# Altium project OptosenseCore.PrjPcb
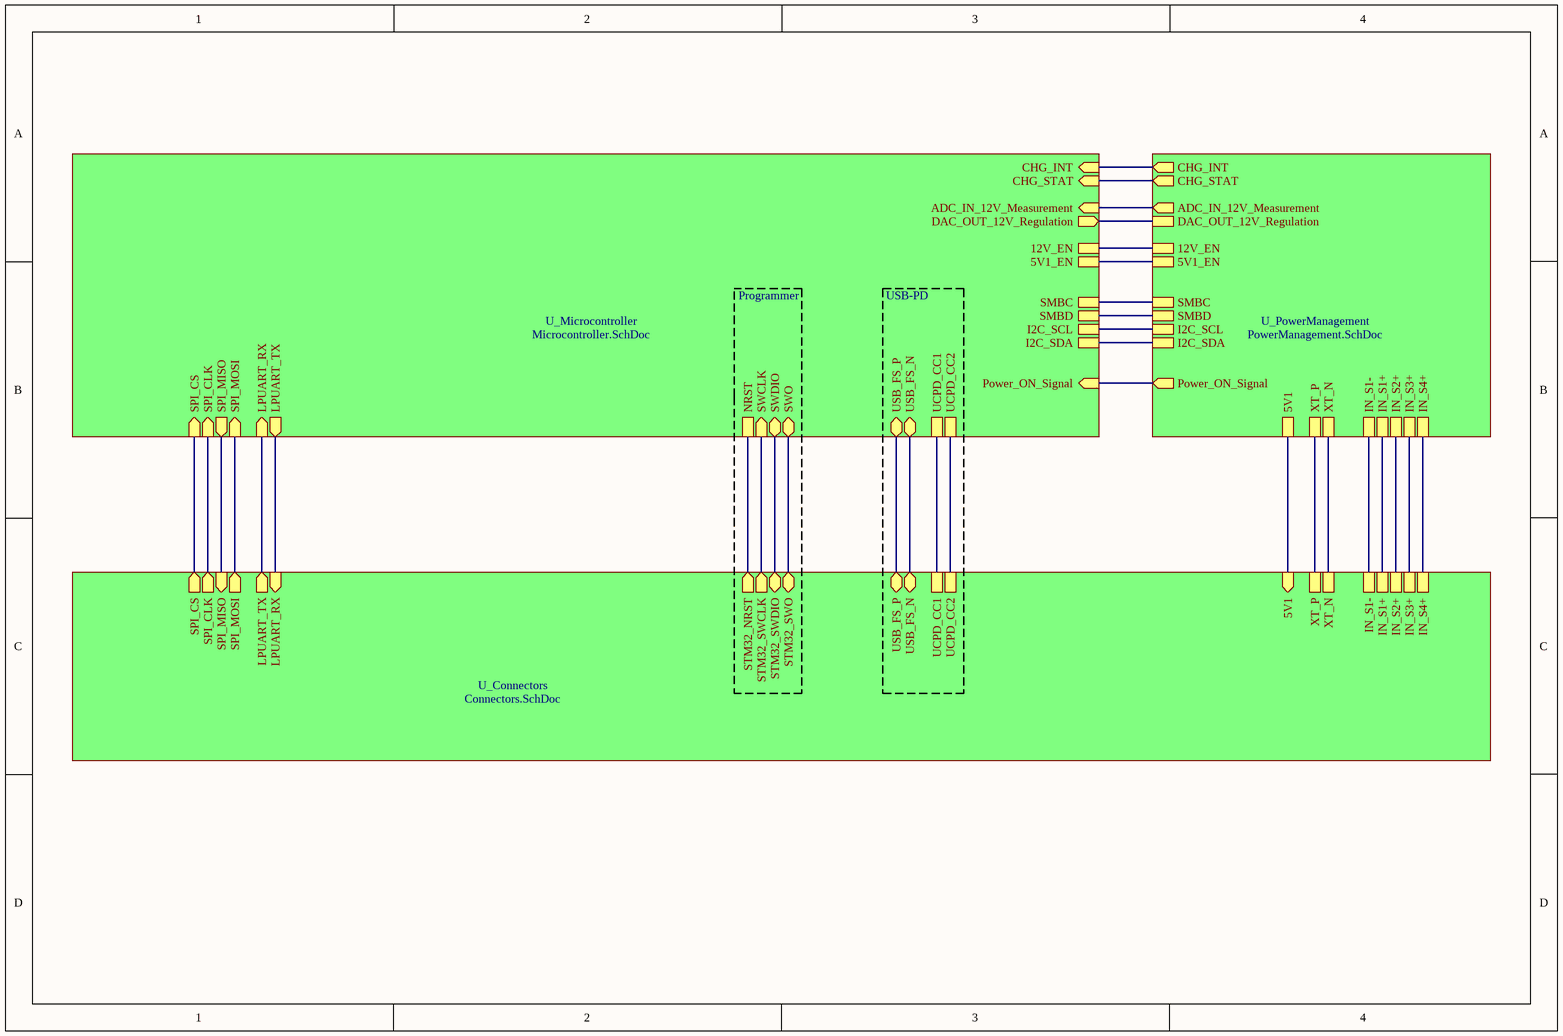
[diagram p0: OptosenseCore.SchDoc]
4 sheets, 184 parts. Net scope: hierarchical (ports join the sheet entries above them; power ports are global).
Board file: OptosenseCore.PcbDoc
Sheets:
  OptosenseCore.SchDoc
    U_Connectors = Connectors.SchDoc
    U_PowerManagement = PowerManagement.SchDoc
    U_Microcontroller = Microcontroller.SchDoc

## Sheet OptosenseCore.SchDoc
size A4

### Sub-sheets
U_Connectors = Connectors.SchDoc: 5V1 (in), SPI_CLK (out), SPI_MISO (in), SPI_MOSI (out), SPI_CS (out), STM32_SWDIO (bidir), STM32_SWO (bidir), STM32_SWCLK (out), USB_FS_P (bidir), USB_FS_N (bidir), UCPD_CC1, UCPD_CC2, LPUART_TX (out), LPUART_RX (in), STM32_NRST (out), XT_P, IN_S2+, IN_S3+, IN_S4+, IN_S1-, XT_N, IN_S1+
U_Microcontroller = Microcontroller.SchDoc: SWO (bidir), SWDIO (bidir), LPUART_RX (in), LPUART_TX (out), SPI_MISO (out), SPI_CLK (in), SPI_CS (in), SPI_MOSI (in), SWCLK (in), UCPD_CC1, UCPD_CC2, USB_FS_P (bidir), USB_FS_N (bidir), DAC_OUT_12V_Regulation (out), I2C_SCL, NRST, I2C_SDA, SMBC, SMBD, 12V_EN, 5V1_EN, CHG_INT (in), Power_ON_Signal (in), CHG_STAT (in), ADC_IN_12V_Measurement (in)
U_PowerManagement = PowerManagement.SchDoc: IN_S3+, IN_S4+, IN_S1-, IN_S1+, IN_S2+, XT_P, XT_N, I2C_SDA, SMBC, SMBD, I2C_SCL, 5V1, 12V_EN, DAC_OUT_12V_Regulation, 5V1_EN, CHG_INT (out), Power_ON_Signal (out), CHG_STAT (out), ADC_IN_12V_Measurement (out)

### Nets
CHG_INT: sheet U_PowerManagement/CHG_INT, sheet U_Microcontroller/CHG_INT
DIFF_USB_FS_N: sheet U_Connectors/USB_FS_N, sheet U_Microcontroller/USB_FS_N
DIFF_USB_FS_P: sheet U_Connectors/USB_FS_P, sheet U_Microcontroller/USB_FS_P
I2C_SCL: sheet U_PowerManagement/I2C_SCL, sheet U_Microcontroller/I2C_SCL
I2C_SDA: sheet U_PowerManagement/I2C_SDA, sheet U_Microcontroller/I2C_SDA
IO.PA0: sheet U_PowerManagement/ADC_IN_12V_Measurement, sheet U_Microcontroller/ADC_IN_12V_Measurement
IO.PA2: sheet U_Connectors/LPUART_RX, sheet U_Microcontroller/LPUART_TX
IO.PA3: sheet U_Connectors/LPUART_TX, sheet U_Microcontroller/LPUART_RX
IO.PA4: sheet U_PowerManagement/DAC_OUT_12V_Regulation, sheet U_Microcontroller/DAC_OUT_12V_Regulation
IO.PA5: sheet U_Connectors/SPI_CLK, sheet U_Microcontroller/SPI_CLK
IO.PA6: sheet U_Connectors/SPI_MISO, sheet U_Microcontroller/SPI_MISO
IO.PA7: sheet U_Connectors/SPI_MOSI, sheet U_Microcontroller/SPI_MOSI
IO.PA8: sheet U_PowerManagement/5V1_EN, sheet U_Microcontroller/5V1_EN
IO.PA10: sheet U_PowerManagement/12V_EN, sheet U_Microcontroller/12V_EN
IO.PA13: sheet U_Connectors/STM32_SWDIO, sheet U_Microcontroller/SWDIO
IO.PA14: sheet U_Connectors/STM32_SWCLK, sheet U_Microcontroller/SWCLK
IO.PA15: sheet U_Connectors/UCPD_CC1, sheet U_Microcontroller/UCPD_CC1
IO.PB0: sheet U_Connectors/SPI_CS, sheet U_Microcontroller/SPI_CS
IO.PB2: sheet U_PowerManagement/CHG_STAT, sheet U_Microcontroller/CHG_STAT
IO.PB3: sheet U_Connectors/STM32_SWO, sheet U_Microcontroller/SWO
IO.PB10: sheet U_PowerManagement/SMBC, sheet U_Microcontroller/SMBC
IO.PB11: sheet U_PowerManagement/SMBD, sheet U_Microcontroller/SMBD
IO.PB14: sheet U_Connectors/UCPD_CC2, sheet U_Microcontroller/UCPD_CC2
IO.PC13: sheet U_PowerManagement/Power_ON_Signal, sheet U_Microcontroller/Power_ON_Signal
NRST: sheet U_Connectors/STM32_NRST, sheet U_Microcontroller/NRST
XT_N: sheet U_Connectors/IN_S1-, sheet U_Connectors/XT_N, sheet U_PowerManagement/IN_S1-, sheet U_PowerManagement/XT_N
XT_P: sheet U_Connectors/XT_P, sheet U_Connectors/IN_S4+, sheet U_PowerManagement/IN_S4+, sheet U_PowerManagement/XT_P
NetR44_1: sheet U_Connectors/IN_S3+, sheet U_PowerManagement/IN_S3+
NetR45_1: sheet U_Connectors/IN_S2+, sheet U_PowerManagement/IN_S2+
NetR46_1: sheet U_Connectors/IN_S1+, sheet U_PowerManagement/IN_S1+
(unnamed): sheet U_Connectors/5V1, sheet U_PowerManagement/5V1

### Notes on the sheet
- Programmer
- USB-PD

## Sheet Connectors.SchDoc
size A3
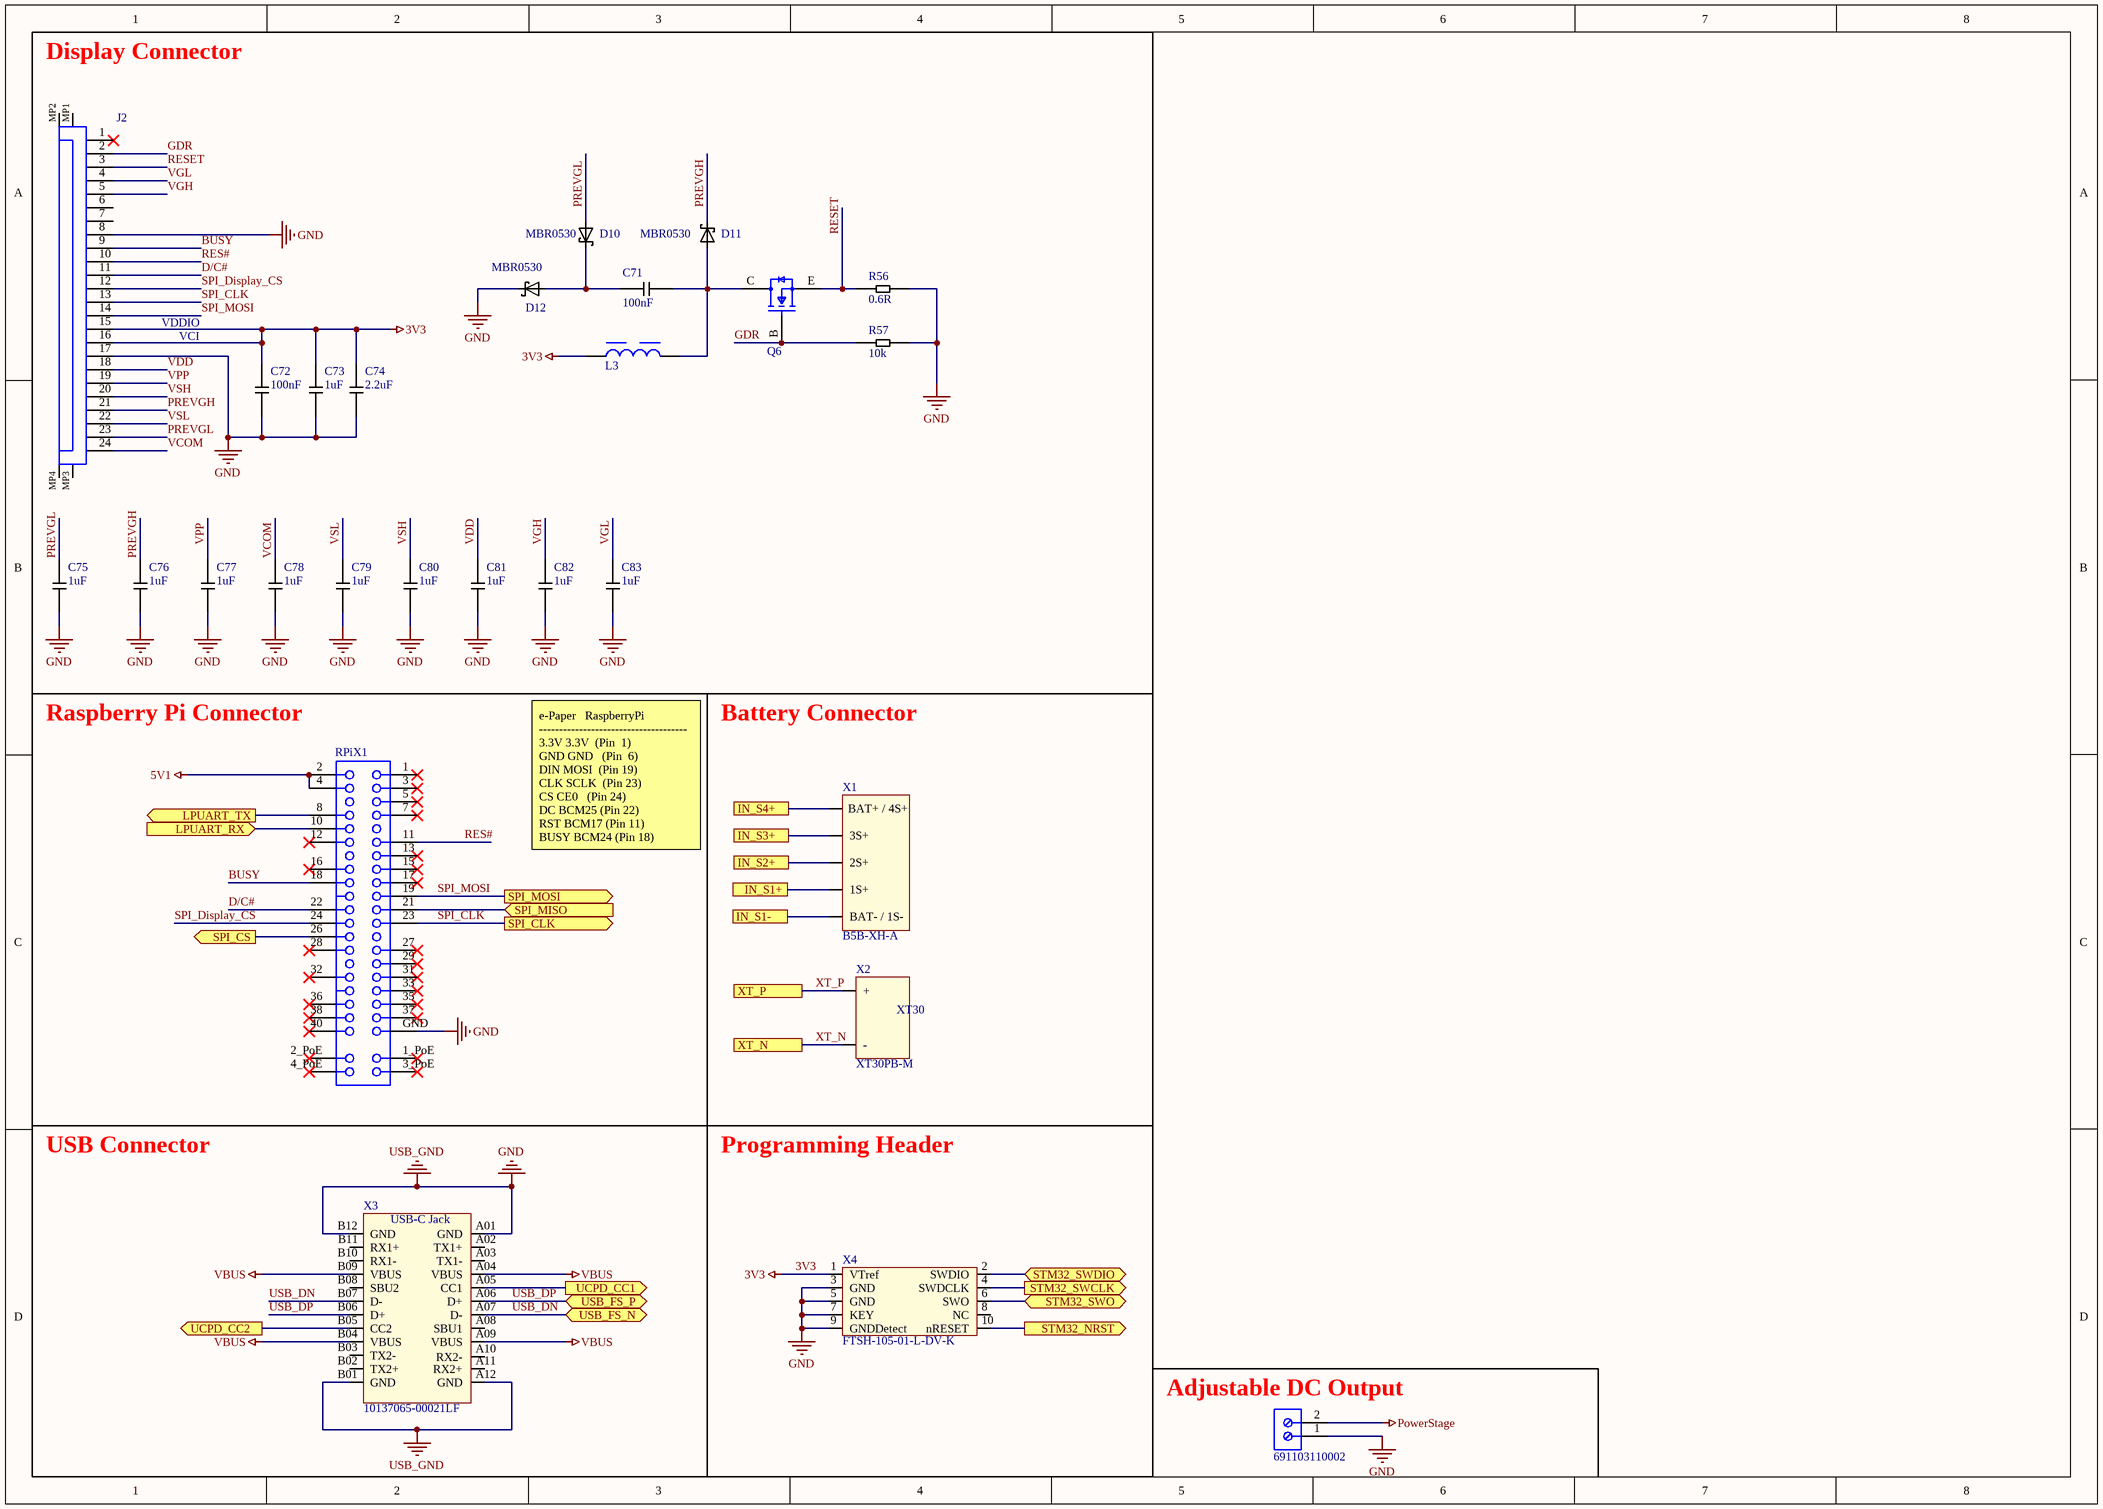
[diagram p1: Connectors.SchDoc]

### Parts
C71  100nF  [C_0402]
C72  100nF  [C_0402]
C73  1uF  [C_0402]
C74  2.2uF  [C_0402]
C75  1uF  [C_0402]
C76  1uF  [C_0402]
C77  1uF  [C_0402]
C78  1uF  [C_0402]
C79  1uF  [C_0402]
C80  1uF  [C_0402]
C81  1uF  [C_0402]
C82  1uF  [C_0402]
C83  1uF  [C_0402]
D10  MBR0530  [*SOD123_MBR0530(Primary)]
D11  MBR0530  [*SOD123_MBR0530(Primary)]
D12  MBR0530  [*SOD123_MBR0530(Primary)]
J2  (no value)  [687324124422]
J_Interlock1  691103110002  [691103110002]
L3  68µH, 0.45A  [WE-LQS_4012]  (value not drawn)
Q6  *  [SOT-23-3]  (value not drawn)
R56  0.6R  [R_0402]
R57  10k  [R_0402]
RPiX1  (no value)  [RPi - PoE Hole]
X1  B5B-XH-A  [X_XH5]
X2  XT30PB-M  [X_XT30_90°]
X3  10137065-00021LF  [X_USBC_JACK]
X4  FTSH-105-01-L-DV-K  [SAMTEC_FTSH-105-01-L-DV-K]

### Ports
IN_S1+, IN_S1-, IN_S2+, IN_S3+, IN_S4+, LPUART_RX (in), LPUART_TX (out), SPI_CLK (out), SPI_CS (out), SPI_MISO (in), SPI_MOSI (out), STM32_NRST (out), STM32_SWCLK (out), STM32_SWDIO (bidir), STM32_SWO (bidir), UCPD_CC1 (out), UCPD_CC2 (out), USB_FS_N (bidir), USB_FS_P (bidir), XT_N, XT_P

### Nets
3V3: C72.2 C73.2 C74.2 J2.15 J2.16 L3.1 X4.1(VTref)
5V1: RPiX1.2 RPiX1.4
GND: C72.1 C73.1 C74.1 C75.1 C76.1 C77.1 C78.1 C79.1 C80.1 C81.1 C82.1 C83.1 D12.C J2.8 J2.17 J_Interlock1.1 R56.1 R57.1 RPiX1.GND X3.A01(GND) X3.A12(GND) X3.B01(GND) X3.B12(GND) X4.3(GND) X4.5(GND) X4.7(KEY) X4.9(GNDDetect)  [also labelled USB_GND]
PowerStage: J_Interlock1.2
VBUS: X3.A04(VBUS) X3.A09(VBUS) X3.B04(VBUS) X3.B09(VBUS)
BUSY: J2.9 RPiX1.18
D/C#: J2.11 RPiX1.22
GDR: J2.2 Q6.B(Gate) R57.2
IO.PA2: RPiX1.10 ; port LPUART_RX
IO.PA3: RPiX1.8 ; port LPUART_TX
IO.PA6: RPiX1.21 ; port SPI_MISO
IO.PA13: X4.2(SWDIO) ; port STM32_SWDIO
IO.PA14: X4.4(SWDCLK) ; port STM32_SWCLK
IO.PA15: X3.A05(CC1) ; port UCPD_CC1
IO.PB0: RPiX1.26 ; port SPI_CS
IO.PB3: X4.6(SWO) ; port STM32_SWO
IO.PB14: X3.B05(CC2) ; port UCPD_CC2
NRST: X4.10(nRESET) ; port STM32_NRST
PREVGH: C76.2 D11.C J2.21
PREVGL: C75.2 D10.A J2.23
RES#: J2.10 RPiX1.11
RESET: J2.3 Q6.E(Source) R56.2
SPI_CLK: J2.13 RPiX1.23 ; port SPI_CLK  [project net IO.PA5]
SPI_Display_CS: J2.12 RPiX1.24
SPI_MOSI: J2.14 RPiX1.19 ; port SPI_MOSI  [project net IO.PA7]
USB_DN: X3.A07(D-) X3.B07(D-) ; port USB_FS_N  [project net DIFF_USB_FS_N]
USB_DP: X3.A06(D+) X3.B06(D+) ; port USB_FS_P  [project net DIFF_USB_FS_P]
VCOM: C78.2 J2.24
VDD: C81.2 J2.18
VGH: C82.2 J2.5
VGL: C83.2 J2.4
VPP: C77.2 J2.19
VSH: C80.2 J2.20
VSL: C79.2 J2.22
XT_N: X1.1(BAT-_/_1S-) X2.2(-) ; port XT_N, port IN_S1-
XT_P: X1.5(BAT+_/_4S+) X2.1(+) ; port XT_P, port IN_S4+
NetC71_1: C71.1 D11.A L3.2 Q6.C
NetC71_2: C71.2 D10.C D12.A
NetR44_1: X1.4(3S+) ; port IN_S3+
NetR45_1: X1.3(2S+) ; port IN_S2+
NetR46_1: X1.2(1S+) ; port IN_S1+

Not connected (* = marked no-connect by the designer): J2 1* 6 7 MP1 MP2 MP3 MP4; RPiX1 1* 1_PoE* 2_PoE* 3* 3_PoE* 4_PoE* 5* 7* 12* 13* 15* 16* 17* 27* 28* 29* 31* 32* 33* 35* 36* 37* 38* 40*; X3 A02(TX1+) A03(TX1-) A08(SBU1) A10(RX2-) A11(RX2+) B02(TX2+) B03(TX2-) B08(SBU2) B10(RX1-) B11(RX1+); X4 8(NC)

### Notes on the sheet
- Display Connector
- VDDIO
- VCI
- (near RPiX1) Raspberry Pi Connector
- Battery Connector
- e-Paper  	RaspberryPi
  -------------------------------------
  3.3V	3.3V 	(Pin  1)
  GND	GND  	(Pin  6)
  DIN	MOSI 	(Pin 19)
  CLK	SCLK 	(Pin 23)
  CS	CE0  	(Pin 24)
  DC	BCM25	(Pin 22)
  RST	BCM17	(Pin 11)
  BUSY	BCM24	(Pin 18)
- USB Connector
- Programming Header
- (near J_Interlock1) Adjustable DC Output

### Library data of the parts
C71 C72 C74 = C_X_0402
C73 C75-C83 = C_X_0402: 50V
D10-D12 = MBR0530: BAT54W-HG3-08
J2 = 687324124422: WR-FPC SMT ZIF Vertical, pitch 0.5mm, 24p; Contact Resistance: 20mOhm; Pin Number: 24; Working Voltage: 50VAC; Rated Current: 0.5A
J_Interlock1 = 691103110002: WR-TBL Serie 1031 Horizontal Entry Modular, Pressure Clamp, THT, pitch 3.5mm, 2p; Manufacturer: Wurth Elektronik; Modularity: Yes; PCB/Cable/Panel: PCB; Pin Number: 2; Rated Current [UL]: 10A; Working Voltage [UL]: 125VAC
L3 = 74404041680: WE-LQS SMT Power Inductor, size 4012, 68µH, 0.45A, 1.495Ω; Manufacturer: Wurth Elektronik; Case/Size Code: 4012; Saturation Current: 0.48A; Self Resonant Frequency: 13MHz
Q6 = NTR4170NT1G
R56 R57 = R_X_0402
RPiX1 = RPi: WR-PHD Socket Header, SMT, pitch 2.54mm, Dual Row, Vertical, 40pin; Part Number: 61004021821; Pin Number: 40; Gender: Female; Rated Current: 3A; Working Voltage: 250VAC; Withstanding Voltage: 600VAC; Contact Resistance: 20mOhm
X1 = X_XH5
X2 = X_XT30PB-F-90°: XT30PB-F-90°
X3 = X_USB_TypC
X4 = X_Cortex_Debug_10

## Sheet PowerManagement.SchDoc
size A2
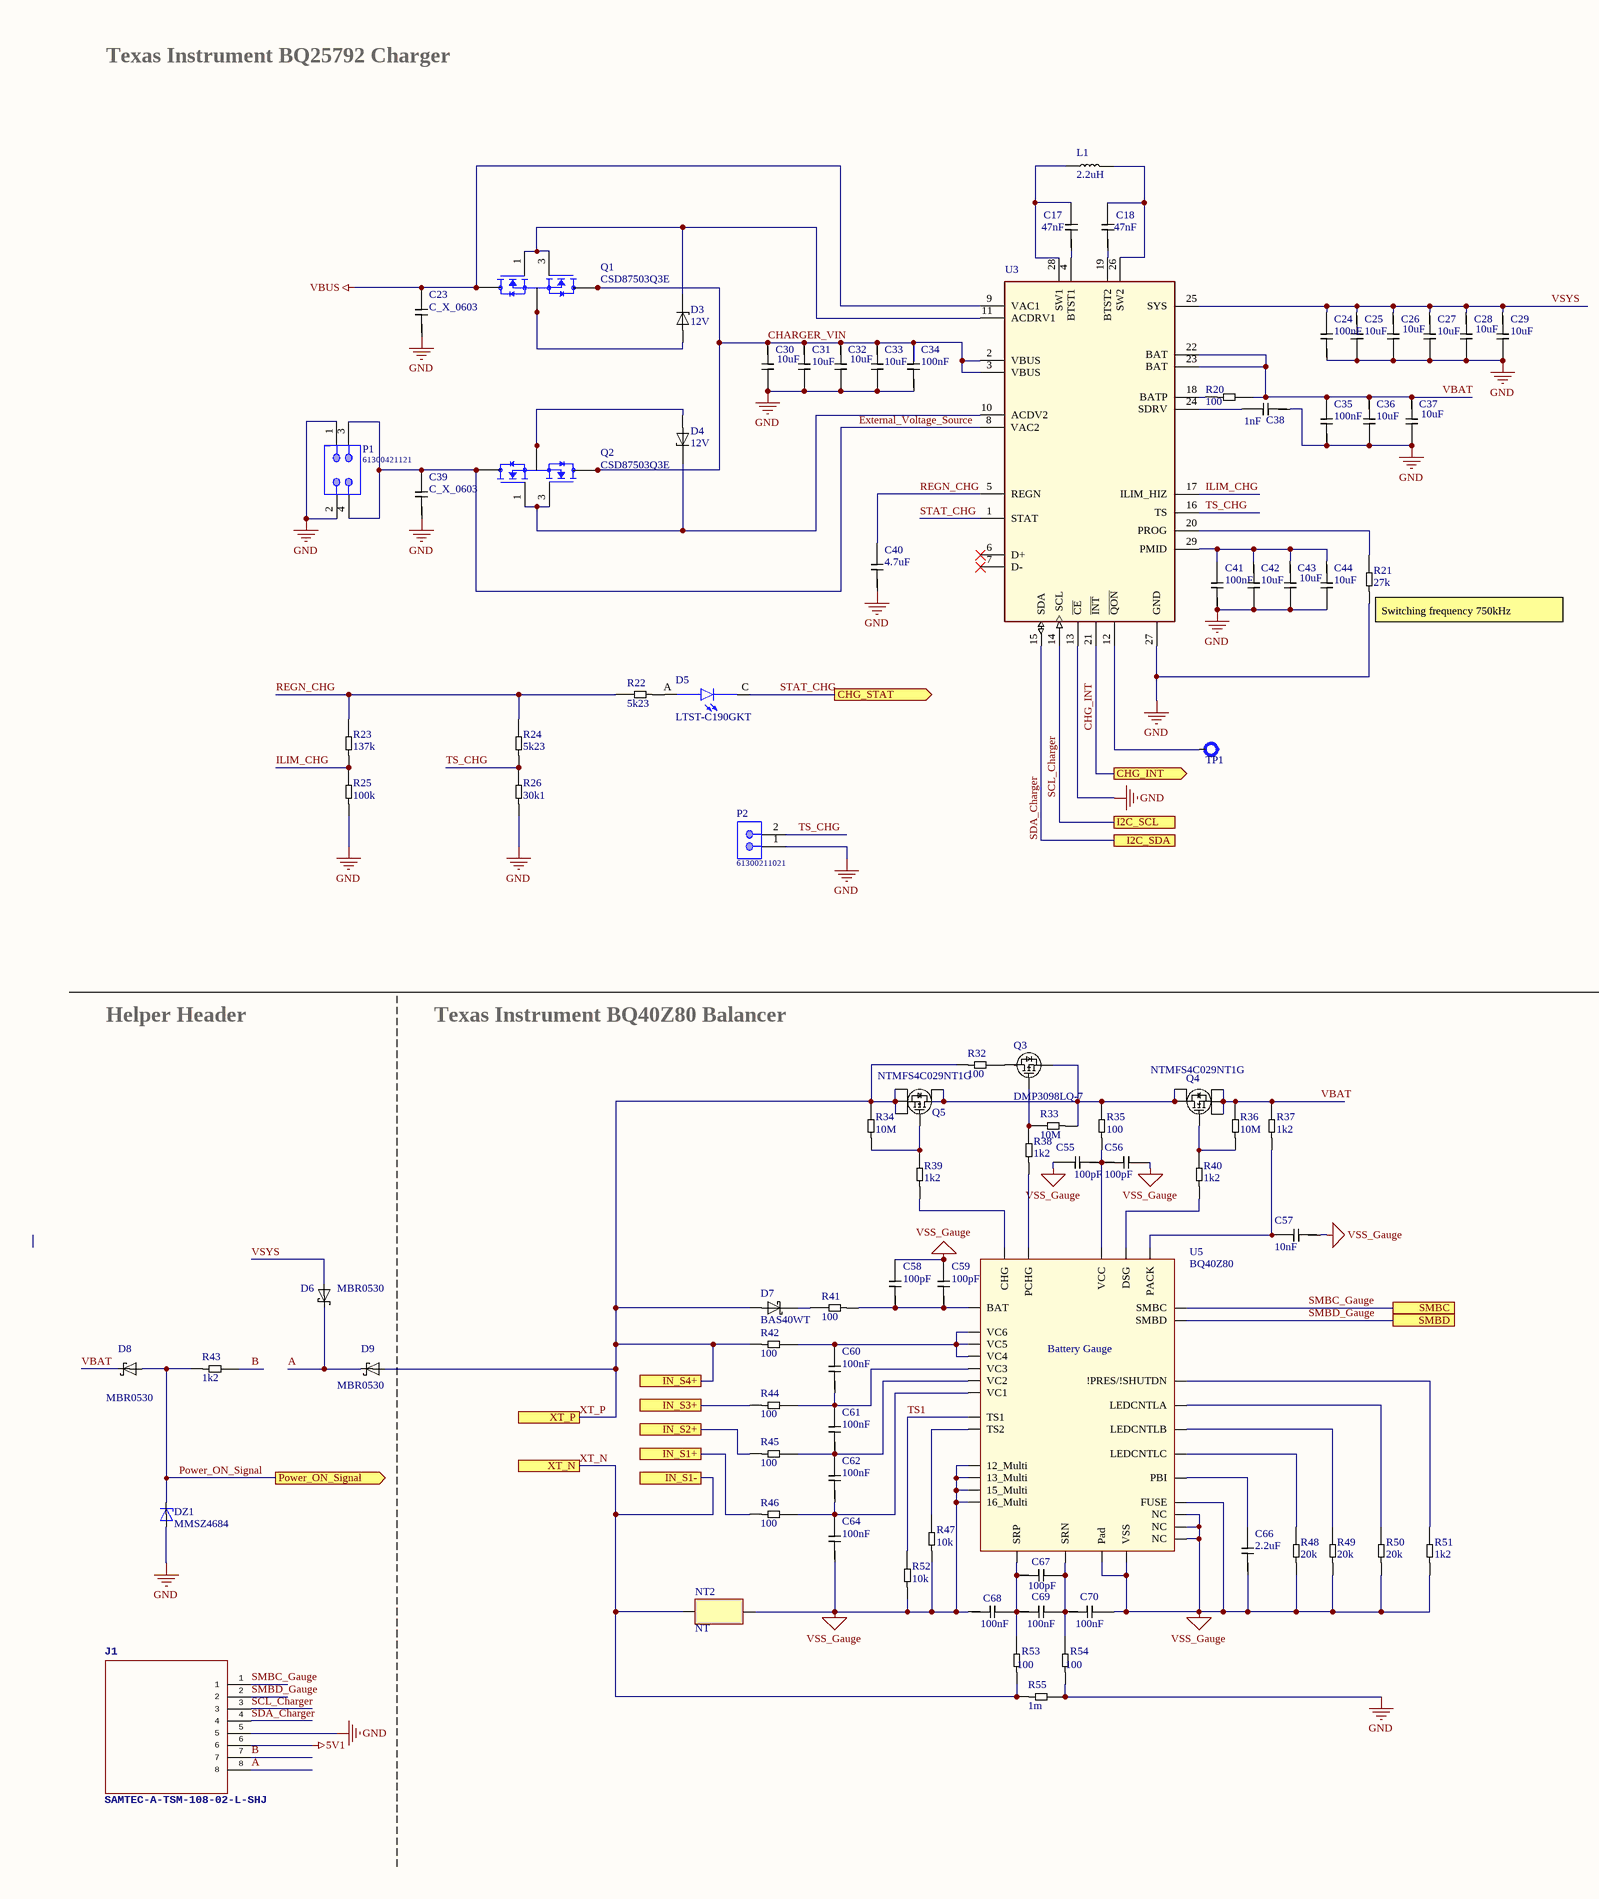
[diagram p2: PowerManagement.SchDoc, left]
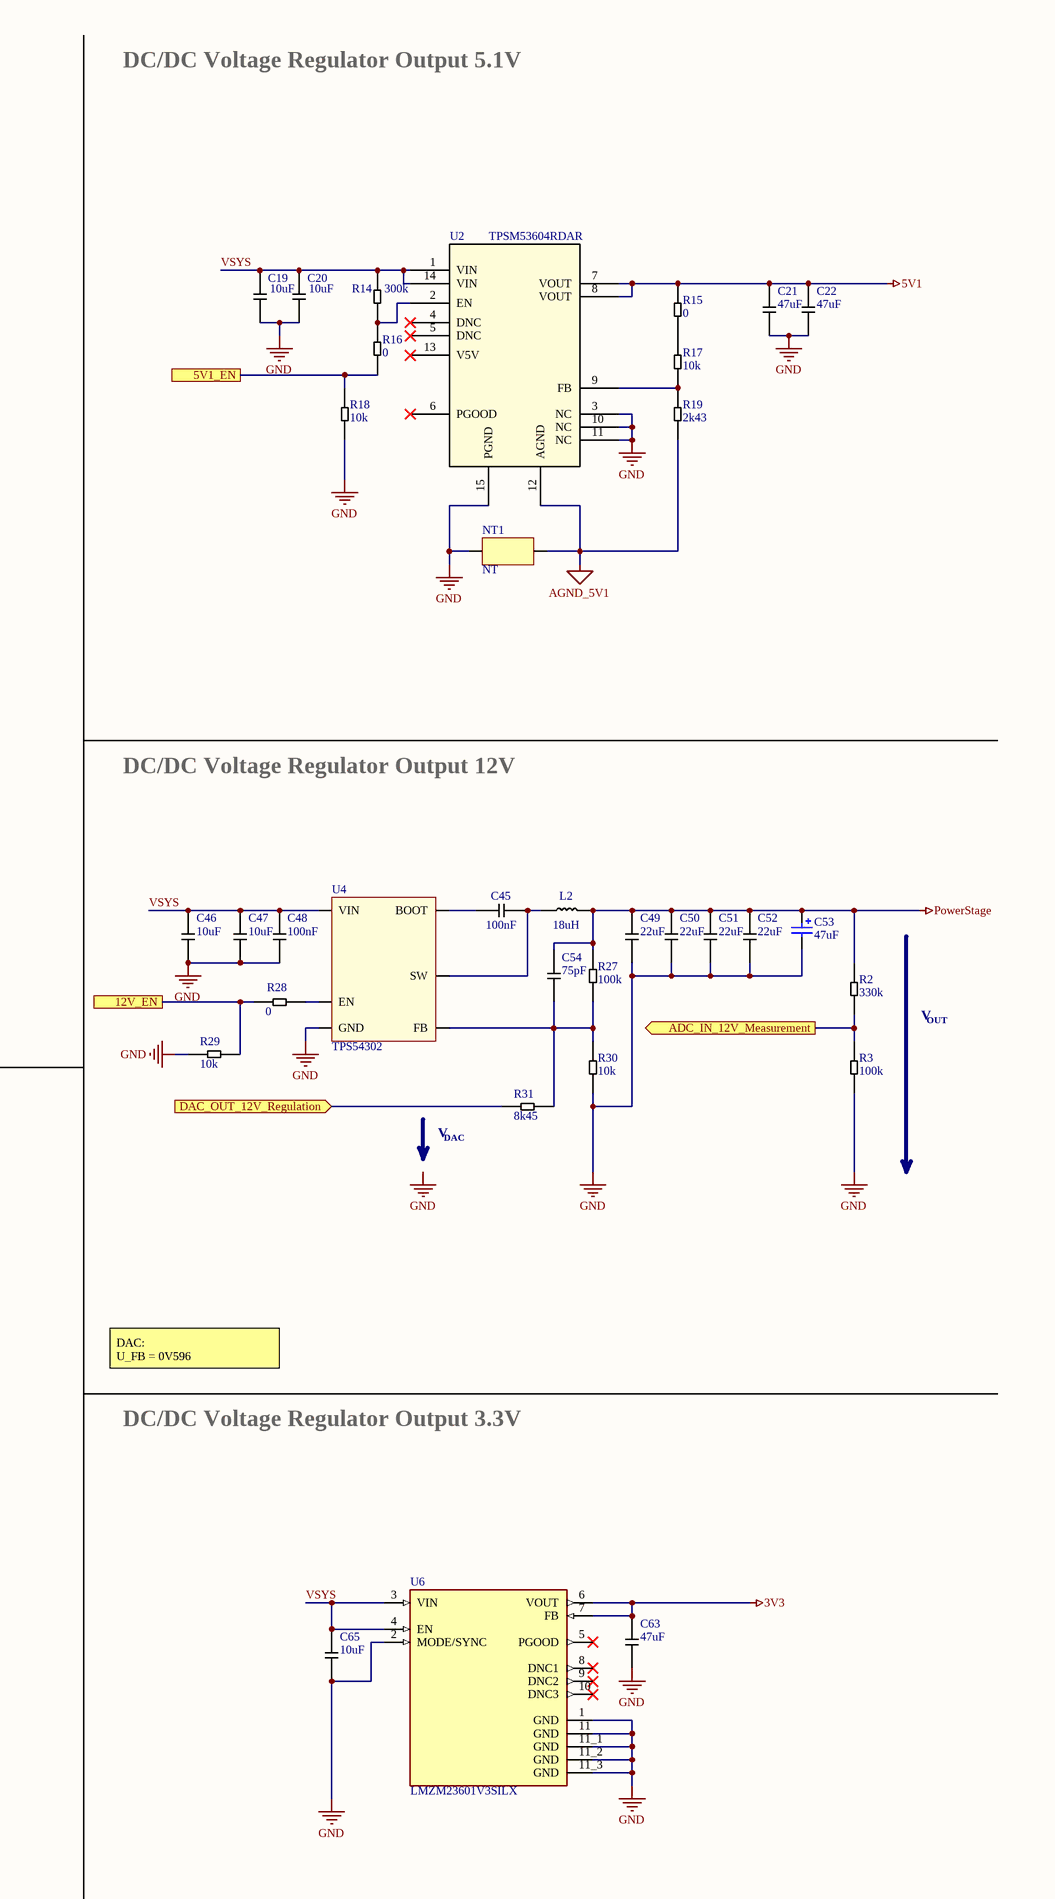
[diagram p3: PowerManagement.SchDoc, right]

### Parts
C17  47nF  [C_0603]
C18  47nF  [C_0603]
C19  10uF  [C_0805]
C20  10uF  [C_0805]
C21  47uF  [C_0805]
C22  47uF  [C_0805]
C23  C_X_0603  [C_0603]
C24  100nF  [C_0402]
C25  10uF  [C_0805]
C26  10uF  [C_0805]
C27  10uF  [C_0805]
C28  10uF  [C_0805]
C29  10uF  [C_0805]
C30  10uF  [C_0805]
C31  10uF  [C_0805]
C32  10uF  [C_0805]
C33  10uF  [C_0805]
C34  100nF  [C_0402]
C35  100nF  [C_0402]
C36  10uF  [C_0805]
C37  10uF  [C_0805]
C38  1nF  [C_0402]
C39  C_X_0603  [C_0603]
C40  4.7uF  [C_0805]
C41  100nF  [C_0402]
C42  10uF  [C_0805]
C43  10uF  [C_0805]
C44  10uF  [C_0805]
C45  100nF  [C_0402]
C46  10uF  [C_0805]
C47  10uF  [C_0805]
C48  100nF  [C_0402]
C49  22uF  [C_1206]
C50  22uF  [C_1206]
C51  22uF  [C_1206]
C52  22uF  [C_1206]
C53  47uF  [WCAP-ASLI_D6.3H5.5]
C54  75pF  [C_0402]
C55  100pF  [C_0402]
C56  100pF  [C_0402]
C57  10nF  [C_0402]
C58  100pF  [C_0402]
C59  100pF  [C_0402]
C60  100nF  [C_0402]
C61  100nF  [C_0402]
C62  100nF  [C_0402]
C63  47uF  [C_0805]
C64  100nF  [C_0402]
C65  10uF  [C_0805]
C66  2.2uF  [C_1210]
C67  100pF  [C_0402]
C68  100nF  [C_0402]
C69  100nF  [C_0402]
C70  100nF  [C_0402]
D3  12V  [MELF_SOD-80]
D4  12V  [MELF_SOD-80]
D5  LTST-C190GKT  [LEDM1608X80]
D6  MBR0530  [*SOD123_MBR0530(Primary)]
D7  BAS40WT  [SOT-323]
D8  MBR0530  [*SOD123_MBR0530(Primary)]
D9  MBR0530  [*SOD123_MBR0530(Primary)]
DZ1  MMSZ4684  [SOD-123]
J1  SAMTEC-A-TSM-108-02-L-SHJ  [SAMTEC-A-TSM-108-02-L-SH]
L1  2.2uH  [MPXV1D0630L2R2]
L2  18uH  [SRN1060]
NT1  NT  [Net Tie]  (net tie, no BOM)
NT2  NT  [Net Tie]  (net tie, no BOM)
P1  61300421121  [61300421121]
P2  61300211021  [61300211021]
Q1  CSD87503Q3E  [CSD87503Q3E]
Q2  CSD87503Q3E  [CSD87503Q3E]
Q3  DMP3098LQ-7  [SOT-23-3]
Q4  NTMFS4C029NT1G  [SO-8FL]
Q5  NTMFS4C029NT1G  [SO-8FL]
R2  330k  [R_0402]
R3  100k  [R_0402]
R14  300k  [R_0402]
R15  0  [R_0402]
R16  0  [R_0402]
R17  10k  [R_0402]
R18  10k  [R_0402]
R19  2k43  [R_0402]
R20  100  [R_0402]
R21  27k  [R_0402]
R22  5k23  [R_0402]
R23  137k  [R_0402]
R24  5k23  [R_0402]
R25  100k  [R_0402]
R26  30k1  [R_0402]
R27  100k  [R_0402]
R28  0  [R_0402]
R29  10k  [R_0402]
R30  10k  [R_0402]
R31  8k45  [R_0402]
R32  100  [R_0508_reversed]
R33  10M  [R_0402]
R34  10M  [R_0402]
R35  100  [R_0402]
R36  10M  [R_0402]
R37  1k2  [R_0402]
R38  1k2  [R_0402]
R39  1k2  [R_0402]
R40  1k2  [R_0402]
R41  100  [R_0402]
R42  100  [R_0402]
R43  1k2  [R_0402]
R44  100  [R_0402]
R45  100  [R_0402]
R46  100  [R_0402]
R47  10k  [R_0402]
R48  20k  [R_0402]
R49  20k  [R_0402]
R50  20k  [R_0402]
R51  1k2  [R_0402]
R52  10k  [R_0402]
R53  100  [R_0402]
R54  100  [R_0402]
R55  1m  [R_1206]
TP1  TP  [Testpoint]  (value not drawn)
U2  TPSM53604RDAR  [Texas_Instruments_RDA0015A_MFG]
U3  BQ25792RQMR  [Texas_Instruments_RQM0029A_MFG]  (value not drawn)
U4  TPS54302  [SOT-23-THIN]
U5  BQ40Z80  [VQFN32]
U6  LMZM23601V3SILX  [CONV_LMZM23601V3XXXX]

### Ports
5V1_EN, 12V_EN, ADC_IN_12V_Measurement (out), CHG_INT (out), CHG_STAT (out), DAC_OUT_12V_Regulation (in), I2C_SCL, I2C_SDA, IN_S1+, IN_S1-, IN_S2+, IN_S3+, IN_S4+, Power_ON_Signal (out), SMBC, SMBD, XT_N, XT_P

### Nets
3V3: C63.2 U6.6(VOUT) U6.7(FB)
5V1: C21.2 C22.2 J1.6 R15.2 U2.7(VOUT) U2.8(VOUT)
AGND_5V1: NT1.2 R19.1 U2.12(AGND)
GND: C19.2 C20.2 C21.1 C22.1 C23.1 C24.1 C25.2 C26.2 C27.2 C28.2 C29.2 C30.2 C31.2 C32.2 C33.2 C34.1 C35.1 C36.2 C37.2 C38.1 C39.1 C40.1 C41.1 C42.2 C43.2 C44.2 C46.2 C47.2 C48.1 C49.2 C50.2 C51.2 C52.2 C53.2(N) C63.1 C65.1 DZ1.A J1.5 NT1.1 P1.1 P1.2 P2.1 R3.2 R18.2 R21.1 R25.1 R26.1 R29.2 R30.1 R54.1 R55.2 U2.3(NC) U2.10(NC) U2.11(NC) U2.15(PGND) U3.13(~{CE}) U3.27(GND) U4.1(GND) U6.1(GND) U6.2(MODE/SYNC) U6.11(GND) U6.11_1(GND) U6.11_2(GND) U6.11_3(GND)
PowerStage: C49.1 C50.1 C51.1 C52.1 C53.1(P) C54.2 L2.2 R2.2 R27.2
VBUS: C23.2 Q1.9(D1) Q1.9.1(D1) Q1.9.2(D1) U3.9(VAC1)
VSS_Gauge: C55.2 C56.2 C57.1 C58.2 C59.2 C64.1 C66.1 C68.1 C70.2 NT2.2 R47.1 R48.1 R49.1 R50.1 R51.1 R52.1 U5.7(NC) U5.9(VSS) U5.12(12_Multi) U5.13(13_Multi) U5.14(NC) U5.15(15_Multi) U5.16(16_Multi) U5.23(FUSE) U5.27(NC) U5.33(Pad)
A: D6.C D9.C J1.8
B: J1.7 R43.2
CHARGER_VIN: C30.1 C31.1 C32.1 C33.1 C34.2 Q1.10(D2) Q1.10.1(D2) Q1.10.2(D2) Q2.10(D2) Q2.10.1(D2) Q2.10.2(D2) U3.2(VBUS) U3.3(VBUS)
CHG_INT: U3.21(~{INT}) ; port CHG_INT
External_Voltage_Source: C39.2 P1.3 P1.4 Q2.9(D1) Q2.9.1(D1) Q2.9.2(D1) U3.8(VAC2)
ILIM_CHG: R23.1 R25.2 U3.17(ILIM_HIZ)
IO.PA0: R2.1 R3.1 ; port ADC_IN_12V_Measurement
IO.PA4: R31.1 ; port DAC_OUT_12V_Regulation
IO.PA8: R16.2 R18.1 ; port 5V1_EN
IO.PA10: R28.2 R29.1 ; port 12V_EN
Power_ON_Signal: D8.A DZ1.C R43.1 ; port Power_ON_Signal  [project net IO.PC13]
REGN_CHG: C40.2 R22.2 R23.2 R24.2 U3.5(REGN)
SCL_Charger: J1.3 U3.14(SCL) ; port I2C_SCL  [project net I2C_SCL]
SDA_Charger: J1.4 U3.15(SDA) ; port I2C_SDA  [project net I2C_SDA]
SMBC_Gauge: J1.1 U5.19(SMBC) ; port SMBC  [project net IO.PB10]
SMBD_Gauge: J1.2 U5.18(SMBD) ; port SMBD  [project net IO.PB11]
STAT_CHG: D5.C U3.1(STAT) ; port CHG_STAT  [project net IO.PB2]
TS1: R52.2 U5.10(TS1)
TS_CHG: P2.2 R24.1 R26.2 U3.16(TS)
VBAT: C35.2 C36.1 C37.1 D8.C Q4.1(S) Q4.2(S) Q4.3(S) R20.2 R36.2 R37.2 U3.22(BAT) U3.23(BAT)
VSYS: C19.1 C20.1 C24.2 C25.1 C26.1 C27.1 C28.1 C29.1 C46.1 C47.1 C48.2 C65.2 D6.A R14.2 U2.1(VIN) U2.14(VIN) U3.25(SYS) U4.3(VIN) U6.3(VIN) U6.4(EN)
XT_N: NT2.1 R53.1 R55.1 ; port IN_S1-, port XT_N
XT_P: D7.1 D9.A Q5.1(S) Q5.2(S) Q5.3(S) R32.1 R34.2 R42.1 ; port IN_S4+, port XT_P
NetC17_1: C17.1 U3.4(BTST1)
NetC17_2: C17.2 L1.1 U3.28(SW1)
NetC18_1: C18.1 U3.19(BTST2)
NetC18_2: C18.2 L1.2 U3.26(SW2)
NetC38_2: C38.2 U3.24(SDRV)
NetC41_2: C41.2 C42.1 C43.1 C44.1 U3.29(PMID)
NetC45_1: C45.1 U4.6(BOOT)
NetC45_2: C45.2 L2.1 U4.2(SW)
NetC54_1: C54.1 R27.1 R30.2 R31.2 U4.4(FB)
NetC55_1: C55.1 C56.1 R35.1 U5.24(VCC)
NetC57_2: C57.2 R37.1 U5.25(PACK)
NetC58_1: C58.1 C59.1 R41.1 U5.30(BAT)
NetC60_1: C60.1 C61.2 R44.2 U5.3(VC3)
NetC60_2: C60.2 R42.2 U5.1(VC5) U5.2(VC4) U5.32(VC6)
NetC61_1: C61.1 C62.2 R45.2 U5.4(VC2)
NetC62_1: C62.1 C64.2 R46.2 U5.5(VC1)
NetC66_2: C66.2 U5.31(PBI)
NetC67_1: C67.1 C68.2 C69.1 R53.2 U5.8(SRP)
NetC67_2: C67.2 C69.2 C70.1 R54.2 U5.6(SRN)
NetD3_1: D3.1 Q1.2(S) Q1.4(S)
NetD3_2: D3.2 Q1.1(G1) Q1.3(G2) U3.11(ACDRV1)
NetD4_1: D4.1 Q2.2(S) Q2.4(S)
NetD4_2: D4.2 Q2.1(G1) Q2.3(G2) U3.10(ACDV2)
NetD5_A: D5.A R22.1
NetD7_3: D7.3 R41.2
NetQ3_B: Q3.B(G) R33.2 R38.2
NetQ3_C: Q3.C(D) R32.2
NetQ3_E: Q3.E(S) Q4.5 Q4.6 Q5.5 Q5.6 R33.1 R35.2
NetQ4_4: Q4.4 R36.1 R40.2
NetQ5_4: Q5.4 R34.1 R39.2
NetR14_1: R14.1 R16.1 U2.2(EN)
NetR15_1: R15.1 R17.2
NetR17_1: R17.1 R19.2 U2.9(FB)
NetR20_1: R20.1 U3.18(BATP)
NetR21_2: R21.2 U3.20(PROG)
NetR28_1: R28.1 U4.5(EN)
NetR38_1: R38.1 U5.28(PCHG)
NetR39_1: R39.1 U5.29(CHG)
NetR40_1: R40.1 U5.26(DSG)
NetR44_1: R44.1 ; port IN_S3+
NetR45_1: R45.1 ; port IN_S2+
NetR46_1: R46.1 ; port IN_S1+
NetR47_2: R47.2 U5.11(TS2)
NetR48_2: R48.2 U5.22(LEDCNTLC)
NetR49_2: R49.2 U5.21(LEDCNTLB)
NetR50_2: R50.2 U5.20(LEDCNTLA)
NetR51_2: R51.2 U5.17(!PRES/!SHUTDN)
NetTP1_1: TP1.1 U3.12(~{QON})

Not connected (* = marked no-connect by the designer): U2 4(DNC)* 5(DNC)* 6(PGOOD)* 13(V5V)*; U3 6(D+)* 7(D-)*; U6 5(PGOOD)* 8(DNC1)* 9(DNC2)* 10(DNC3)*

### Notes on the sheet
- Texas Instrument BQ25792 Charger
- DC/DC Voltage Regulator Output 5.1V
- (near R21) Switching frequency 750kHz
- DC/DC Voltage Regulator Output 12V
- V
- OUT
- Helper Header
- Texas Instrument BQ40Z80 Balancer
- DAC
- DAC:
  U_FB = 0V596
- DC/DC Voltage Regulator Output 3.3V
- Labels drawn without touching a wire or pin: GND

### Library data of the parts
C17 C18 = C_X_0603
C19-C22 C25-C33 C36 C37 C40 C42-C44 C46 C47 C63 C65 = C_X_0805
C24 C34 C35 C38 C41 C45 C48 C54-C62 C64 C67-C70 = C_X_0402
C49-C52 = C_X_1206
C53 = 865080543009: WCAP-ASLI Aluminum Electrolytic Capacitor, V-Chip, SMT, D6.3xH5.5mm, 47uF, 35V; Manufacturer: Wurth Elektronik; Technical Reference: ASED055470M035DVCTBB000; Ripple Current: 240mA; Capacitance Tolerance: +/-20%; Leakage Current: 16.45uA; Endurance: 2000h; Dissipation Factor: 14%; Rated Voltage: 35VDC
C66 = C_X_1210
D3 D4 = D_Zener_SOD-80_12V: 12V BZT55C12-GS08
D5 = LTST-C190GKT: Green 569nm LED Indication - Discrete 2.1V 0603 (1608 Metric); MF: Lite-On Inc.
D6 D8 D9 = MBR0530: BAT54W-HG3-08
D7 = D_Schottky_SOD323_BAS40WT
DZ1 = MMSZ4684: Zener Diode 3.3V 500mW Â±5% Surface Mount SOD-123; MF: ON Semiconductor
L1 = L_2u2_KEMET: MPXV1D0630L2R2
L2 = L_18u: 744066180
NT1 NT2 = Net Tie
P1 = 61300421121: WR-PHD Pin Header, THT, pitch 2.54mm, Dual Row, Vertical, 4p; Manufacturer: Wurth Elektronik; Pin Number: 4; Rated Current: 3A; Working Voltage: 250VAC; Withstanding Voltage: 500VAC; Contact Resistance: 20mOhm
P2 = 61300211021: WR-PHD Pin Header, THT, pitch 2.54mm, Single Row, Angled, 2p; Manufacturer: Wurth Elektronik; Pin Number: 2; Rated Current: 3A; Working Voltage: 250VAC; Withstanding Voltage: 500VAC; Contact Resistance: 20mOhm
Q1 Q2 = CSD87503Q3E: 30V, N ch NexFET MOSFET, dual common source SON3x3, 21.9mOhm 8-VSON -55 to 150; MF: Texas Instruments
Q3 = Q_P-Channel_MOSFET_DMP3098LQ-7
Q4 Q5 = Q_N-Channel_MOSFET_SO-8FL_NTMFS4C029NT1G
R2 R3 R14-R31 R33-R54 = R_X_0402
R32 = R_X_0508
R55 = R_X_1206
TP1 = Testpoint
U2 = TPSM53604RDAR: No Description Available; SourceLibrary: TI_2020-03-16; Built_By: EMA_Cory; Vendor: Texas Instruments
U3 = BQ25792: Battery Charger IC, QFN (29) _4x4_; MF: Texas Instruments
U4 = IC_TPS54302
U5 = IC_BQ40z80
U6 = LMZM23601V3SILX: 4V to 36V, 1A Step-Down Converter Module With Integrated Inductor in 3x3.8x1.6mm Package 10-uSiP -40 to 125; MF: Texas Instruments

## Sheet Microcontroller.SchDoc
size A4
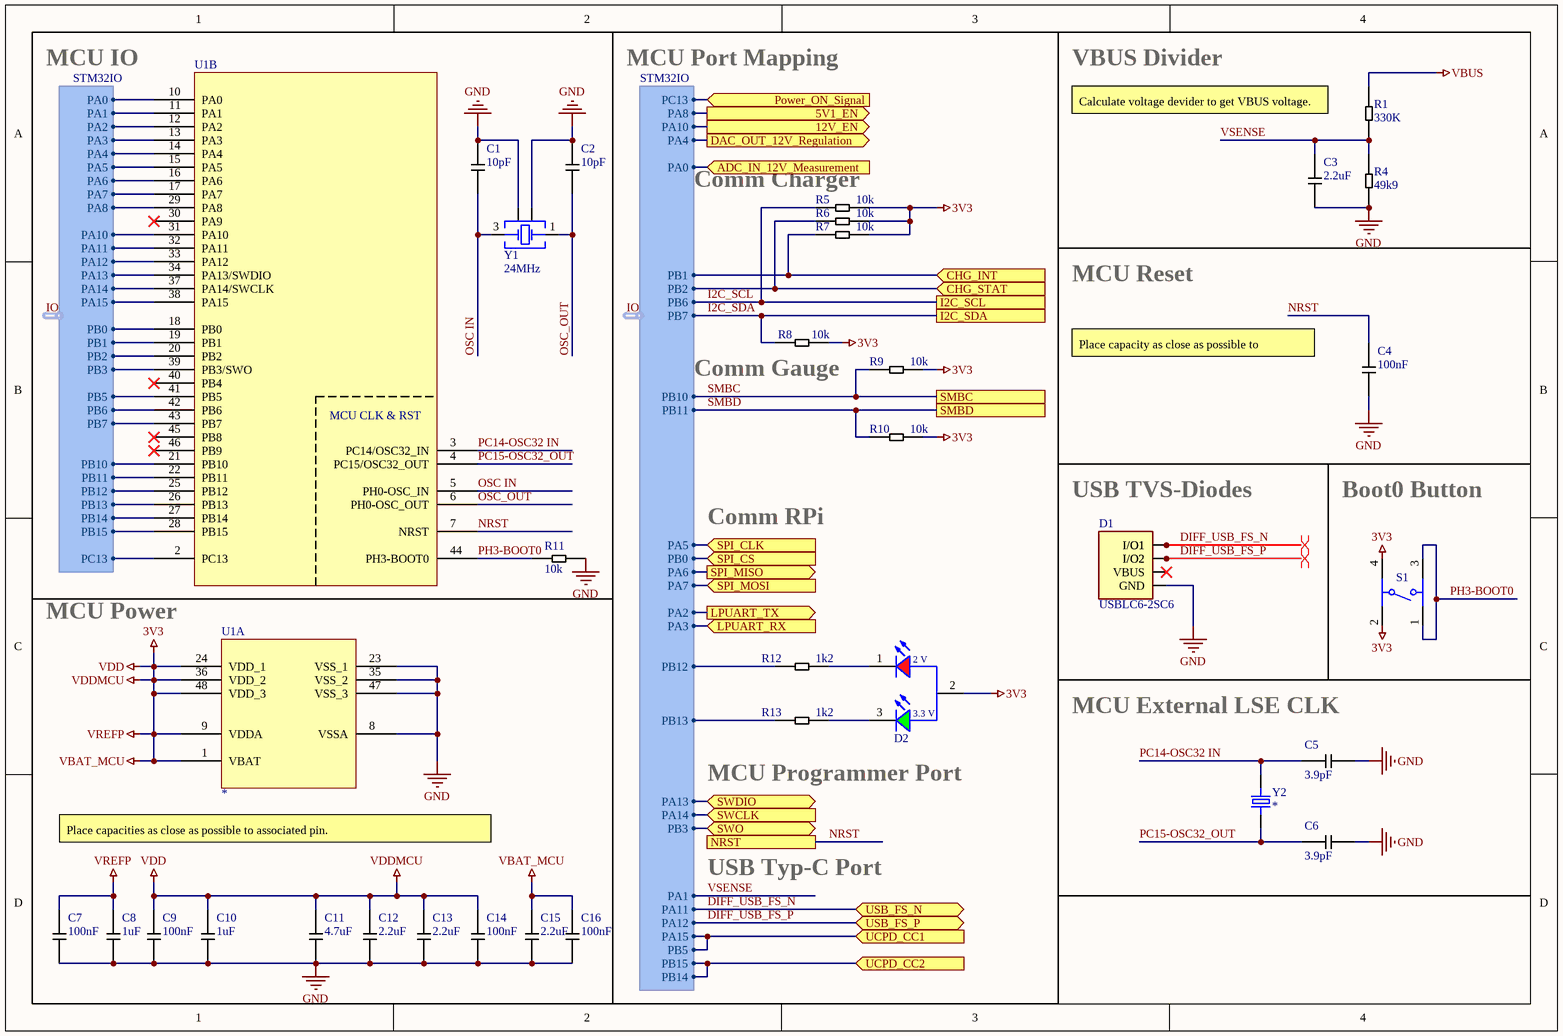
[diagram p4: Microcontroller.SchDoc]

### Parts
C1  10pF  [C_0402]
C2  10pF  [C_0402]
C3  2.2uF  [C_0402]
C4  100nF  [C_0402]
C5  3.9pF  [C_0402]
C6  3.9pF  [C_0402]
C7  100nF  [C_0402]
C8  1uF  [C_0402]
C9  100nF  [C_0402]
C10  1uF  [C_0402]
C11  4.7uF  [C_0402]
C12  2.2uF  [C_0402]
C13  2.2uF  [C_0402]
C14  100nF  [C_0402]
C15  2.2uF  [C_0402]
C16  100nF  [C_0402]
D1  USBLC6-2SC6  [SOT95P280X145-6N]
D2  Red & Green, 120deg  [WL-SBSW_1204]  (value not drawn)
R1  330K  [R_0402]
R4  49k9  [R_0402]
R5  10k  [R_0402]
R6  10k  [R_0402]
R7  10k  [R_0402]
R8  10k  [R_0402]
R9  10k  [R_0402]
R10  10k  [R_0402]
R11  10k  [R_0402]
R12  1k2  [R_0402]
R13  1k2  [R_0402]
S1  434153017835  [434153017835]  (value not drawn)
U1  *  [LQFP-48]  (parts A,B of 2)
Y1  24MHz  [WE-XTAL_IQXC-26]
Y2  *  [XTAL_NX2012SA-32.768K-STD-MUB-1]

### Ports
5V1_EN (out), 12V_EN (out), ADC_IN_12V_Measurement (in), CHG_INT (in), CHG_STAT (in), DAC_OUT_12V_Regulation (out), I2C_SCL, I2C_SDA, LPUART_RX (in), LPUART_TX (out), NRST, Power_ON_Signal (in), SMBC, SMBD, SPI_CLK (in), SPI_CS (in), SPI_MISO (out), SPI_MOSI (in), SWCLK (in), SWDIO (bidir), SWO (bidir), UCPD_CC1 (in), UCPD_CC2 (in), USB_FS_N (bidir), USB_FS_P (bidir)

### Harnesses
STM32IO: PA2, PA3, PA4, PA5, PA6, PA7, PA8, PA10, PA11, PA12, PA13, PA14, PA15, PB0, PB1, PB3, PB5, PB6, PB7, PB10, PB11, PB14, PB15, PB12, PB13, PA0, PA1, PB2, PC13
STM32IO: PA5, PA2, PA3, PA1, PB0, PA6, PA7, PA8, PA10, PA13, PA15, PB3, PB6, PB7, PB10, PB11, PB15, PA11, PA12, PA14, PB5, PB14, PB1, PA4, PB12, PB13, PC13, PA0, PB2

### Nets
3V3: C7.2 C8.2 C9.2 C10.2 C11.2 C12.2 C13.2 C14.2 C15.2 C16.2 D2.2(A) R5.1 R6.1 R7.1 R8.2 R9.1 R10.2 S1.2 S1.4 U1.1(VBAT) U1.9(VDDA) U1.24(VDD_1) U1.36(VDD_2) U1.48(VDD_3)  [also labelled VBAT_MCU, VDD, VDDMCU, VREFP]
GND: C1.1 C2.1 C3.1 C4.1 C5.1 C6.1 C7.1 C8.1 C9.1 C10.1 C11.1 C12.1 C13.1 C14.1 C15.1 C16.1 D1.2(GND) R4.2 R11.1 U1.8(VSSA) U1.23(VSS_1) U1.35(VSS_2) U1.47(VSS_3) Y1.2(GND_&_Lid) Y1.4(GND_&_Lid)
VBUS: R1.2
CHG_INT: R7.2 U1.19(PB1) ; port CHG_INT, harness STM32IO.PB1
DIFF_USB_FS_N: D1.1(I/O1) D1.6(I/O1) U1.32(PA11) ; port USB_FS_N, harness STM32IO.PA11
DIFF_USB_FS_P: D1.3(I/O2) D1.4(I/O2) U1.33(PA12) ; port USB_FS_P, harness STM32IO.PA12
I2C_SCL: R5.2 U1.42(PB6) ; port I2C_SCL, harness STM32IO.PB6
I2C_SDA: R8.1 U1.43(PB7) ; port I2C_SDA, harness STM32IO.PB7
IO.PA0: U1.10(PA0) ; port ADC_IN_12V_Measurement, harness STM32IO.PA0
IO.PA2: U1.12(PA2) ; port LPUART_TX, harness STM32IO.PA2
IO.PA3: U1.13(PA3) ; port LPUART_RX, harness STM32IO.PA3
IO.PA4: U1.14(PA4) ; port DAC_OUT_12V_Regulation, harness STM32IO.PA4
IO.PA5: U1.15(PA5) ; port SPI_CLK, harness STM32IO.PA5
IO.PA6: U1.16(PA6) ; port SPI_MISO, harness STM32IO.PA6
IO.PA7: U1.17(PA7) ; port SPI_MOSI, harness STM32IO.PA7
IO.PA8: U1.29(PA8) ; port 5V1_EN, harness STM32IO.PA8
IO.PA10: U1.31(PA10) ; port 12V_EN, harness STM32IO.PA10
IO.PA13: U1.34(PA13/SWDIO) ; port SWDIO, harness STM32IO.PA13
IO.PA14: U1.37(PA14/SWCLK) ; port SWCLK, harness STM32IO.PA14
IO.PA15: U1.38(PA15) U1.41(PB5) ; port UCPD_CC1, harness STM32IO.PA15, harness STM32IO.PB5
IO.PB0: U1.18(PB0) ; port SPI_CS, harness STM32IO.PB0
IO.PB2: R6.2 U1.20(PB2) ; port CHG_STAT, harness STM32IO.PB2
IO.PB3: U1.39(PB3/SWO) ; port SWO, harness STM32IO.PB3
IO.PB12: R12.1 U1.25(PB12) ; harness STM32IO.PB12
IO.PB13: R13.1 U1.26(PB13) ; harness STM32IO.PB13
IO.PB14: U1.27(PB14) U1.28(PB15) ; port UCPD_CC2, harness STM32IO.PB14, harness STM32IO.PB15
IO.PC13: U1.2(PC13) ; port Power_ON_Signal, harness STM32IO.PC13
NRST: C4.2 U1.7(NRST) ; port NRST
OSC IN: C1.2 U1.5(PH0-OSC_IN) Y1.3(Crystal)
OSC_OUT: C2.2 U1.6(PH0-OSC_OUT) Y1.1(Crystal)
PC14-OSC32 IN: C5.2 U1.3(PC14/OSC32_IN) Y2.1
PC15-OSC32_OUT: C6.2 U1.4(PC15/OSC32_OUT) Y2.2
PH3-BOOT0: R11.2 S1.1 S1.3 U1.44(PH3-BOOT0)
SMBC: R9.2 U1.21(PB10) ; port SMBC, harness STM32IO.PB10  [project net IO.PB10]
SMBD: R10.1 U1.22(PB11) ; port SMBD, harness STM32IO.PB11  [project net IO.PB11]
VSENSE: C3.2 R1.1 R4.1 U1.11(PA1) ; harness STM32IO.PA1  [project net IO.PA1]
NetD2_1: D2.1(K) R12.2
NetD2_3: D2.3(K) R13.2

Not connected (* = marked no-connect by the designer): D1 5(VBUS)*; U1 30(PA9)* 40(PB4)* 45(PB8)* 46(PB9)*

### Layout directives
differential pair; net class USB_FS: DIFF_USB_FS_N, DIFF_USB_FS_P

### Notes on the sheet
- MCU IO
- MCU Port Mapping
- VBUS Divider
- Calculate voltage devider to get VBUS voltage.
- (near R5) Comm Charger
- MCU Reset
- (near R8) Comm Gauge
- Place capacity as close as possible to NRST-Pin.
- (near D1) USB TVS-Diodes
- Boot0 Button
- Comm RPi
- MCU Power
- (near C5) MCU External LSE CLK
- MCU Programmer Port
- Place capacities as close as possible to associated pin.
- USB Typ-C Port

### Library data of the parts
C1-C16 = C_X_0402
D1 = USBLC6-2SC6: 17V Clamp 5A _8/20Âµs_ Ipp Tvs Diode Surface Mount SOT-23-6; MF: STMicroelectronics
D2 = 155124RG73200: WL-SBSW SMT Bi-color Side View Waterclear, size 1204, Red & Green, 120deg; Luminous Intensity: 160mcd@Green, 60mcd@Red; Dominant Wavelength: 525nm@Green, 624nm@Red; Forward Voltage: 3.3V@Green, 2V@Red; Peak Wavelength: 520nm@Green, 632nm@Red; Chip Technology: AlInGaP + InGaN
R1 R4-R13 = R_X_0402
S1 = 434153017835: WS-TASV J-Bend SMT Tact Switch, 3.5x2.9x1.7mm, 350gf; Manufacturer: Wurth Elektronik; Rated Voltage: 12VDC; Rated Current: 50mA; Washable: No
U1 = STM32L552CCXX
Y1 = 830072539: WE-XTAL Quartz Crystal, SMT, IQXC-26, 24MHz, +/-15ppm; Manufacturer: Wurth Elektronik; Load Capacitance: 8pF
Y2 = NX2012SA-32.768K-STD-MUB-1: 32.768kHz Â±20ppm Crystal 12.5pF 80 kOhms 2-SMD, No Lead; MF: NDK America,

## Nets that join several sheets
3V3: Connectors (7 pins), PowerManagement (C63.2 U6.6 U6.7), Microcontroller (24 pins)
5V1: Connectors (RPiX1.2 RPiX1.4), PowerManagement (6 pins)
GND: Connectors (27 pins), PowerManagement (64 pins), Microcontroller (25 pins)
PowerStage: Connectors (J_Interlock1.2), PowerManagement (9 pins)
VBUS: Connectors (X3.A04 X3.A09 X3.B04 X3.B09), PowerManagement (5 pins), Microcontroller (R1.2)
CHG_INT: PowerManagement (U3.21), Microcontroller (R7.2 U1.19)
DIFF_USB_FS_N: Connectors (X3.A07 X3.B07), Microcontroller (D1.1 D1.6 U1.32)
DIFF_USB_FS_P: Connectors (X3.A06 X3.B06), Microcontroller (D1.3 D1.4 U1.33)
I2C_SCL: PowerManagement (J1.3 U3.14), Microcontroller (R5.2 U1.42)
I2C_SDA: PowerManagement (J1.4 U3.15), Microcontroller (R8.1 U1.43)
IO.PA0: PowerManagement (R2.1 R3.1), Microcontroller (U1.10)
IO.PA2: Connectors (RPiX1.10), Microcontroller (U1.12)
IO.PA3: Connectors (RPiX1.8), Microcontroller (U1.13)
IO.PA4: PowerManagement (R31.1), Microcontroller (U1.14)
IO.PA5: Connectors (J2.13 RPiX1.23), Microcontroller (U1.15)
IO.PA6: Connectors (RPiX1.21), Microcontroller (U1.16)
IO.PA7: Connectors (J2.14 RPiX1.19), Microcontroller (U1.17)
IO.PA8: PowerManagement (R16.2 R18.1), Microcontroller (U1.29)
IO.PA10: PowerManagement (R28.2 R29.1), Microcontroller (U1.31)
IO.PA13: Connectors (X4.2), Microcontroller (U1.34)
IO.PA14: Connectors (X4.4), Microcontroller (U1.37)
IO.PA15: Connectors (X3.A05), Microcontroller (U1.38 U1.41)
IO.PB0: Connectors (RPiX1.26), Microcontroller (U1.18)
IO.PB2: PowerManagement (D5.C U3.1), Microcontroller (R6.2 U1.20)
IO.PB3: Connectors (X4.6), Microcontroller (U1.39)
IO.PB10: PowerManagement (J1.1 U5.19), Microcontroller (R9.2 U1.21)
IO.PB11: PowerManagement (J1.2 U5.18), Microcontroller (R10.1 U1.22)
IO.PB14: Connectors (X3.B05), Microcontroller (U1.27 U1.28)
IO.PC13: PowerManagement (D8.A DZ1.C R43.1), Microcontroller (U1.2)
NetR44_1: Connectors (X1.4), PowerManagement (R44.1)
NetR45_1: Connectors (X1.3), PowerManagement (R45.1)
NetR46_1: Connectors (X1.2), PowerManagement (R46.1)
NRST: Connectors (X4.10), Microcontroller (C4.2 U1.7)
XT_N: Connectors (X1.1 X2.2), PowerManagement (NT2.1 R53.1 R55.1)
XT_P: Connectors (X1.5 X2.1), PowerManagement (8 pins)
